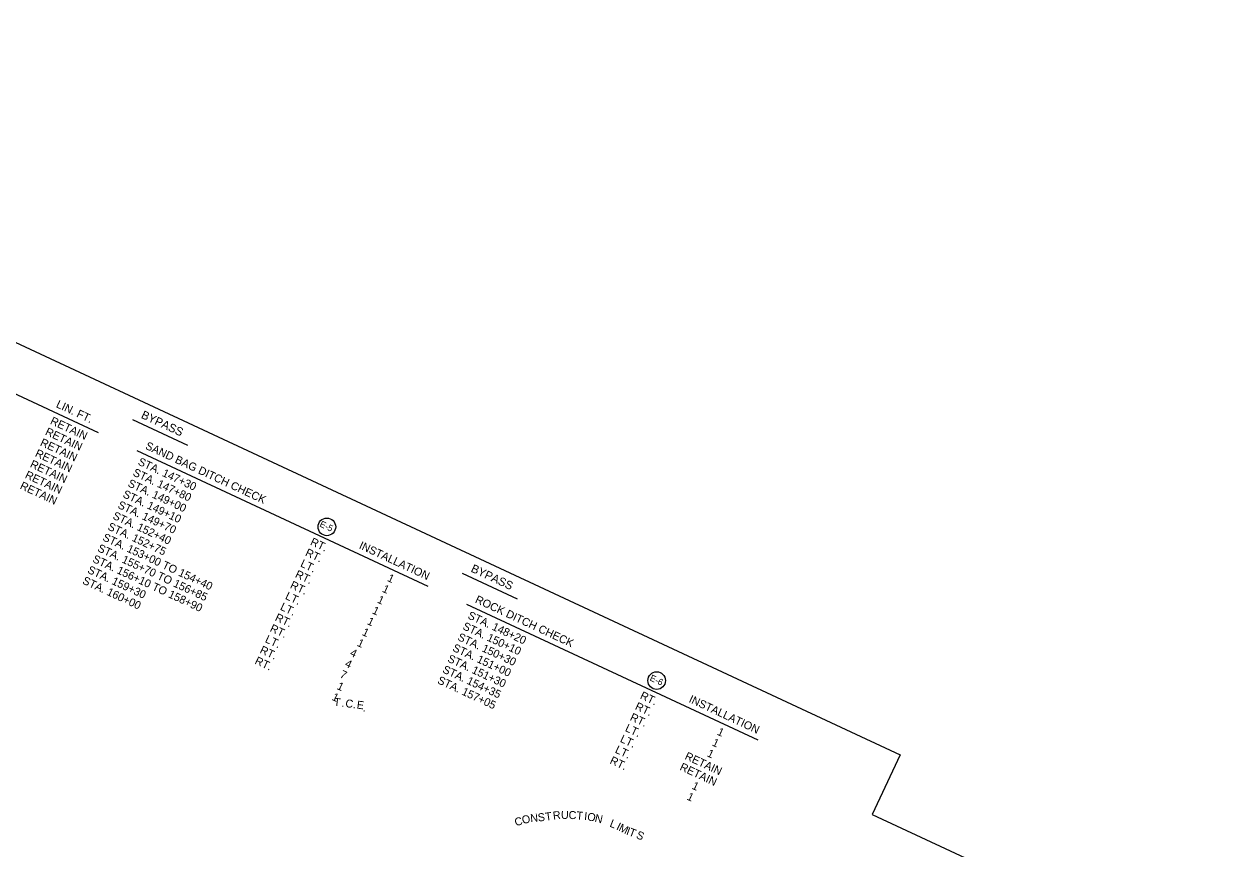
# Model space of a CAD drawing. Extents: x 980231 to 982096, y 1837566 to 1839185.
# Drawn here: x 981190 to 982096, y 1838566 to 1839185 of the extents above; entities that cross this region are included whole.
import ezdxf

# ---------------------------------------------------------------- set-up
doc = ezdxf.new("R2010")
doc.units = 0
for name, color, linetype in [('1', 7, 'Continuous'), ('44', 7, 'Continuous'), ('G-Border-Sheet', 7, 'Continuous'), ('R_Draft', 7, 'Continuous')]:
    doc.layers.add(name, color=color, linetype=linetype)

msp = doc.modelspace()

# ---------------------------------------------------------------- linework, layer by layer
at = {"layer": '1'}
for centre in [(981416.9, 1838807.68), (981664.24, 1838692.35)]:
    msp.add_circle(centre, 6.61, dxfattribs=at)
at = {"layer": '44'}
for p, q in [((981034.41, 1838976.96), (981245.4, 1838878.58)), ((981271.09, 1838888.22), (981312.4, 1838868.95)), ((981274.31, 1838865.1), (981492.73, 1838763.24)), ((981518.43, 1838772.88), (981559.73, 1838753.62)), ((981521.64, 1838749.76), (981740.07, 1838647.91))]:
    msp.add_line(p, q, dxfattribs=at)
at = {"layer": 'G-Border-Sheet'}
msp.add_lwpolyline([(980671.38, 1839184.86), (981846.87, 1838636.72), (981825.93, 1838591.82), (982096.33, 1838465.73), (981897.02, 1838038.3), (981897.02, 1838038.3), (981919.96, 1838087.51), (981609.41, 1838232.32), (981586.46, 1838183.11), (980846.18, 1838528.31), (980876.72, 1838593.79), (980491.54, 1838773.4), (980461.01, 1838707.92), (980451.13, 1838712.53)], close=True, dxfattribs=at)
msp.add_lwpolyline([(980671.38, 1839184.86), (981846.87, 1838636.72), (981825.93, 1838591.82), (982096.33, 1838465.73), (981897.02, 1838038.3), (981897.02, 1838038.3), (981919.96, 1838087.51), (981609.41, 1838232.32), (981586.46, 1838183.11), (980846.18, 1838528.31), (980876.72, 1838593.79), (980491.54, 1838773.4), (980461.01, 1838707.92), (980451.13, 1838712.53)], close=True, dxfattribs=at)
msp.add_lwpolyline([(980671.38, 1839184.86), (981846.87, 1838636.72), (981825.93, 1838591.82), (982096.33, 1838465.73), (981897.02, 1838038.3), (981897.02, 1838038.3), (981919.96, 1838087.51), (981609.41, 1838232.32), (981586.46, 1838183.11), (980846.18, 1838528.31), (980876.72, 1838593.79), (980491.54, 1838773.4), (980461.01, 1838707.92), (980451.13, 1838712.53)], close=True, dxfattribs=at)
msp.add_lwpolyline([(980671.38, 1839184.86), (981846.87, 1838636.72), (981825.93, 1838591.82), (982096.33, 1838465.73), (981897.02, 1838038.3), (981897.02, 1838038.3), (981919.96, 1838087.51), (981609.41, 1838232.32), (981586.46, 1838183.11), (980846.18, 1838528.31), (980876.72, 1838593.79), (980491.54, 1838773.4), (980461.01, 1838707.92), (980451.13, 1838712.53)], close=True, dxfattribs=at)

# ---------------------------------------------------------------- texts
at = {"layer": '1'}
for s, p in [('E-5 ', (981411.04, 1838808.12)), ('E-6 ', (981658.64, 1838692.65))]:
    msp.add_text(s, height=4.8, rotation=335, dxfattribs=at).set_placement(p)
at = {"layer": '44'}
for s, height, rotation, p in [('LIN. FT.', 6, 334.99998, (981213.32, 1838897.68)), ('RETAIN', 6, 334.99998, (981208.93, 1838885.18)), ('BYPASS', 6.25, 335, (981277.08, 1838889.59)), ('RETAIN', 6, 334.99998, (981205.15, 1838877.07)), ('RETAIN', 6, 334.99998, (981201.37, 1838868.96)), ('SAND BAG DITCH CHECK', 6, 335, (981280.24, 1838866.47)), ('RETAIN', 6, 334.99998, (981197.59, 1838860.85)), ('RETAIN', 6, 334.99998, (981193.81, 1838852.74)), ('STA. 147+80', 6, 334.99998, (981270.9, 1838846.44)), ('STA. 147+30', 6, 334.99998, (981274.68, 1838854.55)), ('RETAIN', 6, 334.99998, (981190.02, 1838844.63)), ('STA. 149+00', 6, 334.99998, (981267.11, 1838838.33)), ('RETAIN', 6, 334.99998, (981186.24, 1838836.52)), ('STA. 149+10', 6, 334.99998, (981263.33, 1838830.22)), ('STA. 149+70', 6, 334.99998, (981259.55, 1838822.11)), ('STA. 152+40', 6, 334.99998, (981255.77, 1838814)), ('STA. 152+75', 6, 334.99998, (981251.99, 1838805.89)), ('STA. 153+00 TO 154+40', 6, 334.99998, (981248.2, 1838797.78)), ('RT.', 6, 334.99998, (981403.95, 1838794.43)), ('INSTALLATION', 6, 335, (981440.52, 1838791.73)), ('STA. 155+70 TO 156+85', 6, 334.99998, (981244.42, 1838789.67)), ('RT.', 6, 334.99998, (981400.17, 1838786.32)), ('STA. 156+10 TO 158+90', 6, 334.99998, (981240.64, 1838781.56)), ('LT.', 6, 334.99998, (981396.52, 1838778.15)), ('BYPASS', 6.25, 335, (981524.41, 1838774.26)), ('STA. 160+00', 6, 334.99998, (981233.08, 1838765.34)), ('STA. 159+30', 6, 334.99998, (981236.86, 1838773.45)), ('RT.', 6, 334.99998, (981392.61, 1838770.1)), ('RT.', 6, 334.99998, (981388.82, 1838761.99)), ('LT.', 6, 334.99998, (981385.17, 1838753.82)), ('ROCK DITCH CHECK', 6, 335, (981527.57, 1838751.14)), ('RT.', 6, 334.99998, (981377.48, 1838737.66)), ('LT.', 6, 334.99998, (981381.39, 1838745.71)), ('RT.', 6, 334.99998, (981373.7, 1838729.55)), ('STA. 150+10', 6, 334.99998, (981518.23, 1838731.1)), ('LT.', 6, 334.99998, (981370.04, 1838721.38)), ('STA. 150+30', 6, 334.99998, (981514.45, 1838722.99)), ('RT.', 6, 334.99998, (981366.13, 1838713.33)), ('STA. 151+00', 6, 334.99998, (981510.67, 1838714.88)), ('RT.', 6, 334.99998, (981362.35, 1838705.22)), ('STA. 151+30', 6, 334.99998, (981506.88, 1838706.77)), ('STA. 154+35', 6, 334.99998, (981503.1, 1838698.66)), ('STA. 157+05', 6, 334.99998, (981499.32, 1838690.55)), ('INSTALLATION', 6, 335, (981687.86, 1838676.4)), ('RT.', 6, 334.99998, (981647.5, 1838670.98)), ('RT.', 6, 334.99998, (981643.72, 1838662.87))]:
    msp.add_text(s, height=height, rotation=rotation, dxfattribs=at).set_placement(p)
at = {"layer": 'R_Draft'}
for s, rotation, p in [('1', 334.99998, (981461.74, 1838767.3)), ('1', 334.99998, (981457.95, 1838759.19)), ('1', 334.99998, (981454.17, 1838751.08)), ('1', 334.99998, (981450.39, 1838742.97)), ('STA. 148+20', 334.99998, (981522.01, 1838739.21)), ('1', 334.99998, (981446.61, 1838734.86)), ('1', 334.99998, (981442.83, 1838726.75)), ('4', 334.99998, (981433.72, 1838711.25)), ('1', 334.99998, (981439.05, 1838718.64)), ('4', 334.99998, (981429.94, 1838703.14)), ('7', 334.99998, (981426.16, 1838695.03)), ('1', 334.99998, (981423.92, 1838686.2)), ('1', 334.99998, (981420.14, 1838678.09)), ('T', 352.8891, (981421.82, 1838673.55)), ('RT.', 334.99998, (981651.29, 1838679.09)), ('.', 352.8891, (981427.63, 1838672.83)), ('C', 352.8891, (981430.54, 1838672.47)), ('.', 352.8891, (981436.17, 1838671.76)), ('E', 352.8891, (981439.07, 1838671.4)), ('.', 278.1953, (981444.29, 1838670.61)), ('LT.', 334.99998, (981636.29, 1838646.59)), ('LT.', 334.99998, (981640.07, 1838654.7)), ('1', 334.99998, (981709.07, 1838651.96)), ('LT.', 334.99998, (981632.51, 1838638.48)), ('1', 334.99998, (981705.29, 1838643.85)), ('RT.', 334.99998, (981628.59, 1838630.43)), ('RETAIN', 334.99998, (981684.82, 1838633.65)), ('1', 334.99998, (981701.51, 1838635.74)), ('RETAIN', 334.99998, (981681.03, 1838625.54)), ('1', 334.99998, (981690.16, 1838611.41)), ('1', 334.99998, (981686.38, 1838603.3)), ('C', 15.64679, (981558.61, 1838583.02)), ('O', 15.64679, (981564.07, 1838584.55)), ('N', 5.5016, (981569.73, 1838586.06)), ('S', 5.5016, (981575.37, 1838586.6)), ('T', 7.70749, (981581.01, 1838587.18)), ('R', 7.70749, (981586.81, 1838587.97)), ('U', 359.26447, (981592.44, 1838588.57)), ('C', 359.26447, (981598.2, 1838588.49)), ('T', 354.95654, (981603.87, 1838588.28)), ('I', 354.95654, (981609.7, 1838587.77)), ('O', 347.46102, (981611.7, 1838587.71)), ('N', 347.46102, (981617.42, 1838586.44)), ('L', 338.08748, (981628.51, 1838582.94)), ('I', 333.34949, (981633.47, 1838580.85)), ('M', 333.34949, (981635.24, 1838579.96)), ('I', 339.55931, (981640.96, 1838577.02)), ('T', 339.55931, (981642.82, 1838576.33)), ('S', 337.05763, (981648.35, 1838574.39))]:
    msp.add_text(s, height=6, rotation=rotation, dxfattribs=at).set_placement(p)

doc.saveas('drawing.dxf')
